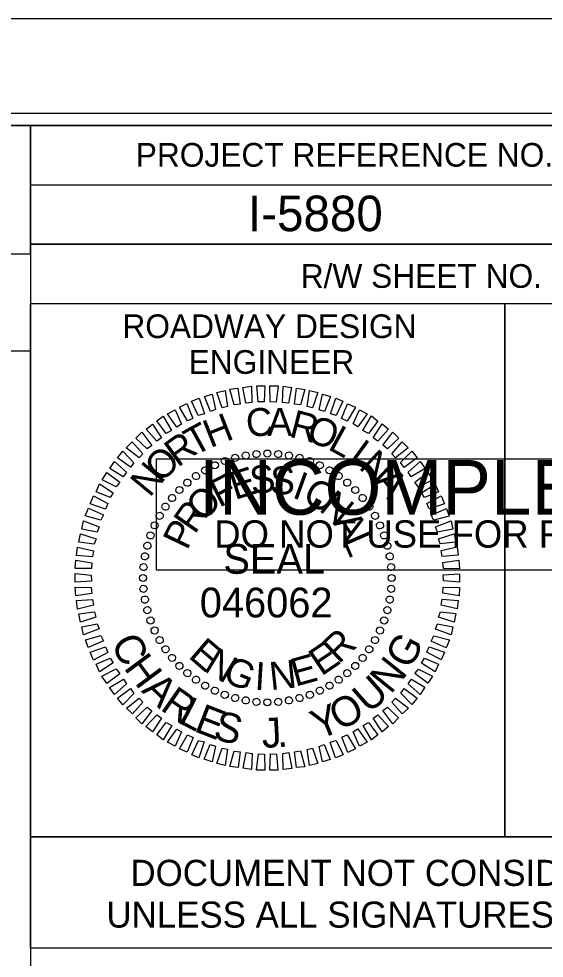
# Model space of a CAD drawing. Extents: x 1639431 to 1641888, y 841916 to 843940.
# Drawn here: x 1641668.3 to 1641779.1, y 842813.2 to 843011.3 of the extents above; entities that cross this region are included whole.
import ezdxf

# ---------------------------------------------------------------- set-up
doc = ezdxf.new("R2010")
doc.units = 0
for name, color, linetype in [('Default', 7, 'Continuous'), ('Old_Level_2', 7, 'Continuous'), ('Prop Dimension Text', 7, 'Continuous'), ('Sheet Data Field CELL', 7, 'Continuous'), ('Sheet Plan CELL', 7, 'Continuous'), ('Sheet Plot Border Inside CELL', 7, 'Continuous'), ('Sheet Plot Border Outside CELL', 7, 'Continuous'), ('Sheet Sticker Exception Certification CELL', 7, 'Continuous'), ('Sheet Sticker Incomplete CELL', 7, 'Continuous')]:
    doc.layers.add(name, color=color, linetype=linetype)

msp = doc.modelspace()

# ---------------------------------------------------------------- linework, layer by layer
at = {"layer": 'Default'}
msp.add_lwpolyline([(1641445.75, 842716.29), (1641445.75, 842941.29), (1641670.75, 842941.29), (1641670.75, 842716.29)], close=True, dxfattribs=at)
at = {"layer": 'Old_Level_2'}
for p, q in [((1641713.88, 842918.72), (1641713.88, 842918.72)), ((1641716.17, 842919.18), (1641716.17, 842919.18)), ((1641718.42, 842919.53), (1641718.42, 842919.53)), ((1641720.72, 842919.62), (1641720.72, 842919.62)), ((1641723.02, 842919.51), (1641723.02, 842919.51)), ((1641725.27, 842919.18), (1641725.27, 842919.18)), ((1641727.48, 842918.75), (1641727.48, 842918.75)), ((1641709.62, 842917.18), (1641709.62, 842917.18)), ((1641711.7, 842918.05), (1641711.7, 842918.05)), ((1641729.69, 842918.05), (1641729.69, 842918.05)), ((1641731.79, 842917.15), (1641731.79, 842917.15)), ((1641705.63, 842914.86), (1641705.63, 842914.86)), ((1641707.6, 842916.1), (1641707.6, 842916.1)), ((1641733.85, 842916.14), (1641733.85, 842916.14)), ((1641735.76, 842914.87), (1641735.76, 842914.87)), ((1641703.83, 842913.52), (1641703.83, 842913.52)), ((1641737.61, 842913.49), (1641737.61, 842913.49)), ((1641700.59, 842910.28), (1641700.59, 842910.28)), ((1641702.13, 842911.92), (1641702.13, 842911.92)), ((1641739.26, 842911.95), (1641739.26, 842911.95)), ((1641740.86, 842910.25), (1641740.86, 842910.25)), ((1641699.21, 842908.42), (1641699.21, 842908.42)), ((1641742.2, 842908.44), (1641742.2, 842908.44)), ((1641697.93, 842906.52), (1641697.93, 842906.52)), ((1641743.43, 842906.47), (1641743.43, 842906.47)), ((1641696.92, 842904.46), (1641696.92, 842904.46)), ((1641744.51, 842904.45), (1641744.51, 842904.45)), ((1641696.02, 842902.35), (1641696.02, 842902.35)), ((1641745.39, 842902.38), (1641745.39, 842902.38)), ((1641695.33, 842900.14), (1641695.33, 842900.14)), ((1641746.05, 842900.19), (1641746.05, 842900.19)), ((1641694.89, 842897.94), (1641694.89, 842897.94)), ((1641746.51, 842897.9), (1641746.51, 842897.9)), ((1641694.57, 842895.69), (1641694.57, 842895.69)), ((1641746.86, 842895.66), (1641746.86, 842895.66)), ((1641694.45, 842893.38), (1641694.45, 842893.38)), ((1641720.7, 842893.37), (1641720.7, 842893.37)), ((1641746.96, 842893.36), (1641746.96, 842893.36)), ((1641694.54, 842891.08), (1641694.54, 842891.08)), ((1641746.84, 842891.05), (1641746.84, 842891.05)), ((1641694.9, 842888.84), (1641694.9, 842888.84)), ((1641746.51, 842888.8), (1641746.51, 842888.8)), ((1641695.35, 842886.55), (1641695.35, 842886.55)), ((1641746.08, 842886.6), (1641746.08, 842886.6)), ((1641696.02, 842884.36), (1641696.02, 842884.36)), ((1641745.39, 842884.39), (1641745.39, 842884.39)), ((1641696.89, 842882.29), (1641696.89, 842882.29)), ((1641744.48, 842882.28), (1641744.48, 842882.28)), ((1641697.97, 842880.27), (1641697.97, 842880.27)), ((1641743.47, 842880.22), (1641743.47, 842880.22)), ((1641699.21, 842878.3), (1641699.21, 842878.3)), ((1641742.2, 842878.32), (1641742.2, 842878.32)), ((1641700.55, 842876.49), (1641700.55, 842876.49)), ((1641702.15, 842874.79), (1641702.15, 842874.79)), ((1641739.28, 842874.82), (1641739.28, 842874.82)), ((1641740.82, 842876.46), (1641740.82, 842876.46)), ((1641703.8, 842873.25), (1641703.8, 842873.25)), ((1641737.58, 842873.22), (1641737.58, 842873.22)), ((1641705.65, 842871.87), (1641705.65, 842871.87)), ((1641707.56, 842870.6), (1641707.56, 842870.6)), ((1641733.81, 842870.64), (1641733.81, 842870.64)), ((1641735.77, 842871.88), (1641735.77, 842871.88)), ((1641709.61, 842869.59), (1641709.61, 842869.59)), ((1641711.72, 842868.69), (1641711.72, 842868.69)), ((1641729.71, 842868.69), (1641729.71, 842868.69)), ((1641731.79, 842869.56), (1641731.79, 842869.56)), ((1641713.93, 842867.99), (1641713.93, 842867.99)), ((1641716.13, 842867.56), (1641716.13, 842867.56)), ((1641718.39, 842867.23), (1641718.39, 842867.23)), ((1641720.69, 842867.12), (1641720.69, 842867.12)), ((1641722.99, 842867.21), (1641722.99, 842867.21)), ((1641725.23, 842867.56), (1641725.23, 842867.56)), ((1641727.53, 842868.02), (1641727.53, 842868.02))]:
    msp.add_line(p, q, dxfattribs=at)
for points in [[(1641708.69, 842928.51), (1641707.43, 842931.63), (1641709.04, 842932.13), (1641709.78, 842928.9)], [(1641711.19, 842929.24), (1641710.03, 842932.51), (1641711.8, 842932.91), (1641712.28, 842929.52)], [(1641713.69, 842929.85), (1641712.79, 842933.19), (1641714.51, 842933.37), (1641714.94, 842930.03)], [(1641716.19, 842930.21), (1641715.56, 842933.55), (1641717.33, 842933.79), (1641717.44, 842930.39)], [(1641718.8, 842930.52), (1641718.48, 842933.91), (1641720.21, 842933.89), (1641720.06, 842930.49)], [(1641721.31, 842930.51), (1641721.25, 842933.91), (1641722.98, 842933.89), (1641722.57, 842930.48)], [(1641723.93, 842930.4), (1641724.08, 842933.8), (1641725.81, 842933.52), (1641725.19, 842930.21)], [(1641726.44, 842930.03), (1641726.86, 842933.38), (1641728.59, 842933.15), (1641727.7, 842929.89)], [(1641729.12, 842929.5), (1641729.58, 842932.9), (1641731.37, 842932.52), (1641730.22, 842929.25)], [(1641731.64, 842928.86), (1641732.37, 842932.12), (1641734, 842931.62), (1641732.75, 842928.51)], [(1641703.86, 842926.49), (1641702.14, 842929.39), (1641703.75, 842930.15), (1641705, 842926.98)], [(1641706.14, 842927.63), (1641704.73, 842930.64), (1641706.29, 842931.29), (1641707.44, 842927.97)], [(1641734.01, 842927.96), (1641735.16, 842931.28), (1641736.63, 842930.67), (1641735.22, 842927.62)], [(1641736.38, 842927.01), (1641737.63, 842930.12), (1641739.27, 842929.41), (1641737.54, 842926.45)], [(1641701.64, 842925.2), (1641699.65, 842927.99), (1641701.26, 842928.85), (1641702.62, 842925.84)], [(1641738.81, 842925.85), (1641740.17, 842928.85), (1641741.75, 842927.99), (1641739.81, 842925.24)], [(1641699.36, 842923.85), (1641697.38, 842926.48), (1641698.72, 842927.5), (1641700.5, 842924.5)], [(1641740.87, 842924.47), (1641742.65, 842927.54), (1641744.03, 842926.46), (1641742.03, 842923.86)], [(1641695.34, 842920.59), (1641692.99, 842922.85), (1641694.23, 842924.13), (1641696.32, 842921.34)], [(1641697.4, 842922.25), (1641695.11, 842924.72), (1641696.5, 842925.84), (1641698.38, 842922.95)], [(1641743.04, 842922.94), (1641744.93, 842925.85), (1641746.3, 842924.72), (1641744.05, 842922.23)], [(1641745.06, 842921.36), (1641747.15, 842924.11), (1641748.43, 842922.88), (1641746.06, 842920.59)], [(1641693.64, 842918.73), (1641690.94, 842920.83), (1641692.22, 842922.05), (1641694.46, 842919.58)], [(1641746.97, 842919.56), (1641749.18, 842922.05), (1641750.45, 842920.82), (1641747.77, 842918.74)], [(1641691.85, 842916.71), (1641689.09, 842918.7), (1641690.22, 842920.08), (1641692.56, 842917.67)], [(1641748.83, 842917.71), (1641751.2, 842920.1), (1641752.32, 842918.71), (1641749.58, 842916.68)], [(1641690.31, 842914.7), (1641687.46, 842916.43), (1641688.43, 842917.96), (1641690.98, 842915.7)], [(1641750.44, 842915.7), (1641752.96, 842917.94), (1641753.98, 842916.44), (1641751.08, 842914.71)], [(1641688.78, 842912.58), (1641685.83, 842914.1), (1641686.85, 842915.58), (1641689.6, 842913.54)], [(1641751.83, 842913.58), (1641754.57, 842915.61), (1641755.59, 842914.06), (1641752.58, 842912.54)], [(1641687.57, 842910.31), (1641684.56, 842911.57), (1641685.32, 842913.2), (1641688.18, 842911.32)], [(1641753.23, 842911.3), (1641756.13, 842913.18), (1641756.84, 842911.57), (1641753.88, 842910.32)], [(1641686.56, 842907.89), (1641683.3, 842909.03), (1641684.06, 842910.67), (1641687.06, 842909.05)], [(1641754.32, 842909.07), (1641757.37, 842910.69), (1641758.08, 842909.03), (1641754.86, 842907.93)], [(1641685.56, 842905.57), (1641682.3, 842906.45), (1641682.95, 842908.09), (1641686.11, 842906.68)], [(1641755.3, 842906.63), (1641758.47, 842908.04), (1641759.07, 842906.43), (1641755.84, 842905.54)], [(1641684.82, 842903.05), (1641681.56, 842903.67), (1641681.9, 842905.4), (1641685.22, 842904.15)], [(1641756.18, 842904.13), (1641759.51, 842905.4), (1641759.85, 842903.68), (1641756.57, 842903.04)], [(1641684.18, 842900.52), (1641680.93, 842900.89), (1641681.27, 842902.67), (1641684.58, 842901.63)], [(1641756.85, 842901.64), (1641760.13, 842902.69), (1641760.47, 842900.92), (1641757.19, 842900.54)], [(1641683.81, 842897.85), (1641680.46, 842898.11), (1641680.64, 842899.89), (1641684.05, 842899.11)], [(1641757.37, 842899.14), (1641760.75, 842899.93), (1641760.94, 842898.15), (1641757.6, 842897.88)], [(1641683.59, 842895.34), (1641680.19, 842895.38), (1641680.27, 842897.11), (1641683.67, 842896.59)], [(1641757.72, 842896.63), (1641761.12, 842897.11), (1641761.25, 842895.33), (1641757.85, 842895.38)], [(1641683.58, 842892.72), (1641680.19, 842892.51), (1641680.16, 842894.28), (1641683.56, 842893.98)], [(1641757.82, 842894.02), (1641761.22, 842894.23), (1641761.25, 842892.46), (1641757.84, 842892.76)], [(1641683.68, 842890.11), (1641680.29, 842889.63), (1641680.16, 842891.41), (1641683.56, 842891.36)], [(1641757.82, 842891.4), (1641761.22, 842891.36), (1641761.14, 842889.63), (1641757.73, 842890.15)], [(1641684.04, 842887.61), (1641680.65, 842886.81), (1641680.47, 842888.59), (1641683.81, 842888.86)], [(1641757.6, 842888.89), (1641760.95, 842888.63), (1641760.77, 842886.85), (1641757.36, 842887.63)], [(1641684.55, 842885.1), (1641681.28, 842884.05), (1641680.93, 842885.83), (1641684.22, 842886.2)], [(1641757.23, 842886.22), (1641760.48, 842885.85), (1641760.14, 842884.07), (1641756.83, 842885.11)], [(1641685.23, 842882.61), (1641681.9, 842881.34), (1641681.56, 842883.06), (1641684.84, 842883.7)], [(1641756.59, 842883.69), (1641759.84, 842883.07), (1641759.51, 842881.34), (1641756.19, 842882.59)], [(1641686.11, 842880.11), (1641682.94, 842878.7), (1641682.34, 842880.31), (1641685.56, 842881.2)], [(1641755.85, 842881.17), (1641759.11, 842880.29), (1641758.46, 842878.65), (1641755.29, 842880.06)], [(1641687.09, 842877.67), (1641684.03, 842876.05), (1641683.32, 842877.71), (1641686.55, 842878.81)], [(1641754.85, 842878.85), (1641758.11, 842877.71), (1641757.35, 842876.07), (1641754.34, 842877.69)], [(1641688.17, 842875.44), (1641685.28, 842873.56), (1641684.57, 842875.17), (1641687.53, 842876.42)], [(1641753.84, 842876.43), (1641756.84, 842875.17), (1641756.09, 842873.54), (1641753.23, 842875.42)], [(1641689.57, 842873.16), (1641686.84, 842871.13), (1641685.82, 842872.68), (1641688.82, 842874.2)], [(1641752.63, 842874.16), (1641755.58, 842872.64), (1641754.56, 842871.16), (1641751.81, 842873.2)], [(1641690.97, 842871.04), (1641688.45, 842868.8), (1641687.43, 842870.3), (1641690.33, 842872.03)], [(1641751.09, 842872.04), (1641753.95, 842870.31), (1641752.98, 842868.78), (1641750.43, 842871.04)], [(1641692.57, 842869.03), (1641690.21, 842866.64), (1641689.09, 842868.03), (1641691.82, 842870.06)], [(1641749.56, 842870.03), (1641752.31, 842868.04), (1641751.19, 842866.66), (1641748.84, 842869.07)], [(1641694.44, 842867.18), (1641692.23, 842864.69), (1641690.96, 842865.92), (1641693.64, 842868)], [(1641747.77, 842868.01), (1641750.47, 842865.91), (1641749.18, 842864.69), (1641746.94, 842867.16)], [(1641696.35, 842865.38), (1641694.26, 842862.63), (1641692.98, 842863.86), (1641695.34, 842866.15)], [(1641746.07, 842866.15), (1641748.41, 842863.89), (1641747.18, 842862.61), (1641745.09, 842865.4)], [(1641698.37, 842863.8), (1641696.48, 842860.89), (1641695.1, 842862.02), (1641697.36, 842864.51)], [(1641700.54, 842862.27), (1641698.76, 842859.2), (1641697.38, 842860.28), (1641699.38, 842862.88)], [(1641742.05, 842862.89), (1641744.03, 842860.26), (1641742.69, 842859.24), (1641740.91, 842862.24)], [(1641744.01, 842864.49), (1641746.3, 842862.02), (1641744.91, 842860.9), (1641743.03, 842863.79)], [(1641702.6, 842860.89), (1641701.24, 842857.89), (1641699.66, 842858.75), (1641701.6, 842861.5)], [(1641739.77, 842861.54), (1641741.76, 842858.75), (1641740.15, 842857.89), (1641738.79, 842860.9)], [(1641705.03, 842859.73), (1641703.77, 842856.62), (1641702.14, 842857.33), (1641703.87, 842860.29)], [(1641707.4, 842858.78), (1641706.25, 842855.46), (1641704.78, 842856.07), (1641706.19, 842859.12)], [(1641735.26, 842859.11), (1641736.68, 842856.1), (1641735.12, 842855.45), (1641733.96, 842858.77)], [(1641737.55, 842860.25), (1641739.27, 842857.35), (1641737.66, 842856.59), (1641736.4, 842859.76)], [(1641709.77, 842857.88), (1641709.04, 842854.62), (1641707.41, 842855.12), (1641708.66, 842858.23)], [(1641712.29, 842857.24), (1641711.82, 842853.84), (1641710.04, 842854.22), (1641711.18, 842857.49)], [(1641714.96, 842856.71), (1641714.55, 842853.36), (1641712.82, 842853.59), (1641713.71, 842856.85)], [(1641727.72, 842856.89), (1641728.62, 842853.55), (1641726.89, 842853.37), (1641726.47, 842856.71)], [(1641730.22, 842857.5), (1641731.38, 842854.23), (1641729.6, 842853.83), (1641729.13, 842857.22)], [(1641732.72, 842858.23), (1641733.97, 842855.11), (1641732.36, 842854.61), (1641731.63, 842857.84)], [(1641717.48, 842856.34), (1641717.33, 842852.94), (1641715.6, 842853.22), (1641716.22, 842856.53)], [(1641720.1, 842856.23), (1641720.16, 842852.83), (1641718.43, 842852.85), (1641718.84, 842856.26)], [(1641722.61, 842856.22), (1641722.93, 842852.83), (1641721.2, 842852.85), (1641721.35, 842856.25)], [(1641725.22, 842856.53), (1641725.85, 842853.19), (1641724.08, 842852.95), (1641723.96, 842856.35)]]:
    msp.add_lwpolyline(points, close=True, dxfattribs=at)
for centre, major_axis in [((1641718.42, 842919.5), (-0.066, 0.75)), ((1641720.7, 842919.6), (0, 0.753)), ((1641722.99, 842919.5), (0.066, 0.75)), ((1641711.73, 842918.02), (-0.258, 0.708)), ((1641713.92, 842918.7), (-0.195, 0.727)), ((1641716.15, 842919.2), (-0.131, 0.742)), ((1641725.26, 842919.2), (0.131, 0.742)), ((1641727.49, 842918.7), (0.195, 0.727)), ((1641729.67, 842918.02), (0.258, 0.708)), ((1641707.59, 842916.08), (-0.376, 0.652)), ((1641709.62, 842917.14), (-0.318, 0.682)), ((1641731.79, 842917.14), (0.318, 0.682)), ((1641733.82, 842916.08), (0.376, 0.652)), ((1641703.84, 842913.46), (-0.484, 0.577)), ((1641705.66, 842914.85), (-0.432, 0.617)), ((1641735.75, 842914.85), (0.432, 0.617)), ((1641737.56, 842913.46), (0.484, 0.577)), ((1641702.16, 842911.92), (-0.532, 0.532)), ((1641739.25, 842911.92), (0.532, 0.532)), ((1641700.61, 842910.23), (-0.577, 0.484)), ((1641740.8, 842910.23), (0.577, 0.484)), ((1641699.22, 842908.41), (-0.617, 0.432)), ((1641742.19, 842908.41), (0.617, 0.432)), ((1641697.99, 842906.48), (-0.652, 0.376)), ((1641743.42, 842906.48), (0.652, 0.376)), ((1641696.93, 842904.45), (-0.682, 0.318)), ((1641744.47, 842904.45), (0.682, 0.318)), ((1641696.06, 842902.34), (-0.708, 0.258)), ((1641745.35, 842902.34), (0.708, 0.258)), ((1641695.37, 842900.16), (-0.727, 0.195)), ((1641746.04, 842900.16), (0.727, 0.195)), ((1641694.87, 842897.92), (-0.742, 0.131)), ((1641746.53, 842897.92), (0.742, 0.131)), ((1641694.58, 842895.66), (-0.75, 0.066)), ((1641746.83, 842895.66), (0.75, 0.066)), ((1641694.48, 842893.37), (-0.753, 0)), ((1641746.93, 842893.37), (0.753, 0)), ((1641694.58, 842891.08), (-0.75, -0.066)), ((1641746.83, 842891.08), (0.75, -0.066)), ((1641694.87, 842888.82), (-0.742, -0.131)), ((1641746.53, 842888.82), (0.742, -0.131)), ((1641695.37, 842886.58), (-0.727, -0.195)), ((1641746.04, 842886.58), (0.727, -0.195)), ((1641696.06, 842884.4), (-0.708, -0.258)), ((1641745.35, 842884.4), (0.708, -0.258)), ((1641696.93, 842882.29), (-0.682, -0.318)), ((1641744.47, 842882.29), (0.682, -0.318)), ((1641697.99, 842880.26), (-0.652, -0.376)), ((1641743.42, 842880.26), (0.652, -0.376)), ((1641699.22, 842878.33), (-0.617, -0.432)), ((1641742.19, 842878.33), (0.617, -0.432)), ((1641700.61, 842876.51), (-0.577, -0.484)), ((1641740.8, 842876.51), (0.577, -0.484)), ((1641702.16, 842874.82), (-0.532, -0.532)), ((1641739.25, 842874.82), (0.532, -0.532)), ((1641703.84, 842873.28), (-0.484, -0.577)), ((1641705.66, 842871.89), (-0.432, -0.617)), ((1641735.75, 842871.89), (0.432, -0.617)), ((1641737.56, 842873.28), (0.484, -0.577)), ((1641707.59, 842870.66), (-0.376, -0.652)), ((1641733.82, 842870.66), (0.376, -0.652)), ((1641709.62, 842869.6), (-0.318, -0.682)), ((1641711.73, 842868.72), (-0.258, -0.708)), ((1641713.92, 842868.04), (-0.195, -0.727)), ((1641727.49, 842868.04), (0.195, -0.727)), ((1641729.67, 842868.72), (0.258, -0.708)), ((1641731.79, 842869.6), (0.318, -0.682)), ((1641716.15, 842867.54), (-0.131, -0.742)), ((1641718.42, 842867.24), (-0.066, -0.75)), ((1641720.7, 842867.14), (0, -0.753)), ((1641722.99, 842867.24), (0.066, -0.75)), ((1641725.26, 842867.54), (0.131, -0.742))]:
    msp.add_ellipse(centre, major_axis=major_axis, ratio=0.999708, dxfattribs=at)
at = {"layer": 'Prop Dimension Text'}
msp.add_lwpolyline([(1641520.72, 842961.76), (1641670.75, 842961.76), (1641670.75, 842988.83), (1641520.72, 842988.83)], close=True, dxfattribs=at)
at = {"layer": 'Sheet Plan CELL'}
for p, q in [((1641670.74, 842976.28), (1641870.79, 842976.27)), ((1641670.75, 842963.74), (1641870.79, 842963.77)), ((1641670.75, 842963.74), (1641870.79, 842963.77)), ((1641670.75, 842963.74), (1641670.75, 842951.26)), ((1641770.8, 842951.26), (1641770.81, 842838.79))]:
    msp.add_line(p, q, dxfattribs=at)
for points in [[(1640370.79, 841938.82), (1640370.76, 842988.79), (1641670.75, 842988.83), (1641670.76, 842838.77), (1641870.8, 842838.76), (1641870.8, 841938.82)], [(1641870.83, 842988.82), (1640370.79, 842988.82), (1640370.79, 841938.82), (1641870.8, 841938.82)], [(1641670.75, 842988.83), (1641870.83, 842988.82), (1641870.79, 842963.77), (1641670.75, 842963.74)], [(1641670.75, 842951.26), (1641770.8, 842951.26), (1641770.8, 842838.74), (1641670.76, 842838.77)], [(1641770.8, 842951.26), (1641870.79, 842951.27), (1641870.8, 842838.76), (1641770.8, 842838.74)]]:
    msp.add_lwpolyline(points, close=True, dxfattribs=at)
at = {"layer": 'Sheet Plot Border Inside CELL'}
msp.add_lwpolyline([(1640217.3, 841936.31), (1641883.29, 841936.32), (1641883.3, 842991.31), (1640217.3, 842991.31)], close=True, dxfattribs=at)
at = {"layer": 'Sheet Plot Border Outside CELL'}
msp.add_lwpolyline([(1640204.3, 841916.31), (1641887.8, 841916.31), (1641887.8, 843011.31), (1640204.3, 843011.31)], close=True, dxfattribs=at)
msp.add_lwpolyline([(1640204.3, 841916.31), (1641887.8, 841916.31), (1641887.8, 843011.31), (1640204.3, 843011.31)], close=True, dxfattribs=at)
at = {"layer": 'Sheet Sticker Exception Certification CELL'}
for p, q in [((1641670.76, 842815.27), (1641670.76, 842838.77)), ((1641670.76, 842838.77), (1641870.8, 842838.77)), ((1641670.76, 842815.27), (1641670.76, 842838.77)), ((1641670.76, 842838.77), (1641870.8, 842838.77)), ((1641870.8, 842815.27), (1641670.76, 842815.27)), ((1641870.8, 842815.27), (1641670.76, 842815.27))]:
    msp.add_line(p, q, dxfattribs=at)
at = {"layer": 'Sheet Sticker Incomplete CELL'}
msp.add_lwpolyline([(1641697.3, 842895.01), (1641697.3, 842918.51), (1641844.3, 842918.51), (1641844.3, 842895.01)], close=True, dxfattribs=at)

# ---------------------------------------------------------------- texts
at = {"layer": 'Default'}
for s, rotation, p in [('C', 297.1999, (1641687.58, 842879.64)), ('G', 61.7998, (1641750.82, 842873.87)), ('H', 306.6436, (1641690.28, 842874.39)), ('N', 51.2288, (1641746.73, 842868.68)), ('U', 41.4347, (1641742.15, 842864.61)), ('A', 316.4834, (1641693.97, 842869.47)), ('R', 325.1961, (1641697.9, 842865.69)), ('L', 332.5683, (1641701.64, 842862.99)), ('E', 338.7525, (1641705.02, 842861.12)), ('Y', 22.2426, (1641731.51, 842859.16)), ('O', 30.0413, (1641736.05, 842860.95)), ('S', 345.7591, (1641709.07, 842859.44)), ('J', 3.0321, (1641719.66, 842857.51)), ('.', 8.214, (1641722.9, 842857.57))]:
    msp.add_text(s, height=6.27, rotation=rotation, dxfattribs=at).set_placement(p)
at = {"layer": 'Old_Level_2'}
for s, rotation, p in [('H', 21.6195, (1641708.67, 842920.72)), ('C', 7.2199, (1641716.58, 842922.95)), ('A', 0.0203, (1641720.7, 842923.34)), ('R', 345.6211, (1641725.1, 842923.2)), ('T', 28.8198, (1641705.3, 842918.94)), ('O', 338.4212, (1641728.62, 842922.48)), ('L', 331.2209, (1641733.25, 842920.63)), ('R', 36.0205, (1641701.79, 842916.57)), ('I', 324.0201, (1641737.53, 842918.19)), ('O', 43.2217, (1641698.24, 842913.27)), ('N', 316.8189, (1641739.8, 842916.61)), ('N', 50.4235, (1641695.88, 842910.19)), ('E', 17.6111, (1641713.88, 842909.78)), ('S', 8.2556, (1641717.47, 842910.94)), ('S', 358.9004, (1641721.23, 842911.06)), ('F', 26.967, (1641710.56, 842908.15)), ('I', 340.1896, (1641725.74, 842910.4)), ('A', 309.6172, (1641742.94, 842913.58)), ('O', 45.6812, (1641707.17, 842905)), ('O', 330.8335, (1641727.84, 842909.71)), ('N', 321.4766, (1641731.38, 842907.68)), ('R', 55.0397, (1641705.38, 842902.41)), ('A', 302.7603, (1641734.41, 842905.01)), ('P', 64.3989, (1641703.77, 842899.04)), ('L', 293.4009, (1641736.51, 842901.44)), ('E', 319.2769, (1641703.84, 842876.71)), ('R', 43.4814, (1641735.77, 842875.07)), ('N', 328.634, (1641707.03, 842873.94)), ('E', 34.1241, (1641732.1, 842872.55)), ('E', 15.4118, (1641726.6, 842870.41)), ('G', 337.9902, (1641711.04, 842871.66)), ('I', 356.7012, (1641717.93, 842869.79)), ('N', 6.0564, (1641721.43, 842869.69))]:
    msp.add_text(s, height=5.9, rotation=rotation, dxfattribs=at).set_placement(p)
for s, height, p in [('SEAL', 6.273, (1641711.43, 842894.25)), ('046062', 6.275, (1641706.46, 842885.05))]:
    msp.add_text(s, height=height, dxfattribs=at).set_placement(p)
at = {"layer": 'Sheet Data Field CELL'}
msp.add_text('I-5880', height=7.5, rotation=0, dxfattribs=at).set_placement((1641716.62, 842966.51))
at = {"layer": 'Sheet Plan CELL'}
for s, height, p in [('PROJECT REFERENCE NO.', 5.0001, (1641692.95, 842980.11)), ('R/W SHEET NO.', 5.0001, (1641727.75, 842954.56)), ('ROADWAY DESIGN', 5.0001, (1641690.13, 842943.96)), ('ENGINEER', 5, (1641704.11, 842936.42))]:
    msp.add_text(s, height=height, rotation=0, dxfattribs=at).set_placement(p)
at = {"layer": 'Sheet Sticker Exception Certification CELL'}
for s, p in [('DOCUMENT NOT CONSIDERED FINAL', (1641691.83, 842828.42)), ('DOCUMENT NOT CONSIDERED FINAL', (1641691.83, 842828.42)), ('UNLESS ALL SIGNATURES COMPLETED', (1641686.76, 842819.62)), ('UNLESS ALL SIGNATURES COMPLETED', (1641686.76, 842819.62))]:
    msp.add_text(s, height=5.5, rotation=360, dxfattribs=at).set_placement(p)
at = {"layer": 'Sheet Sticker Incomplete CELL'}
for s, height, p in [('INCOMPLETE PLANS', 11.52, (1641706.25, 842906.71)), ('DO NOT USE FOR R/W ACQUISITION', 5.76, (1641709.5, 842899.76))]:
    msp.add_text(s, height=height, rotation=360, dxfattribs=at).set_placement(p)

doc.saveas('drawing.dxf')
